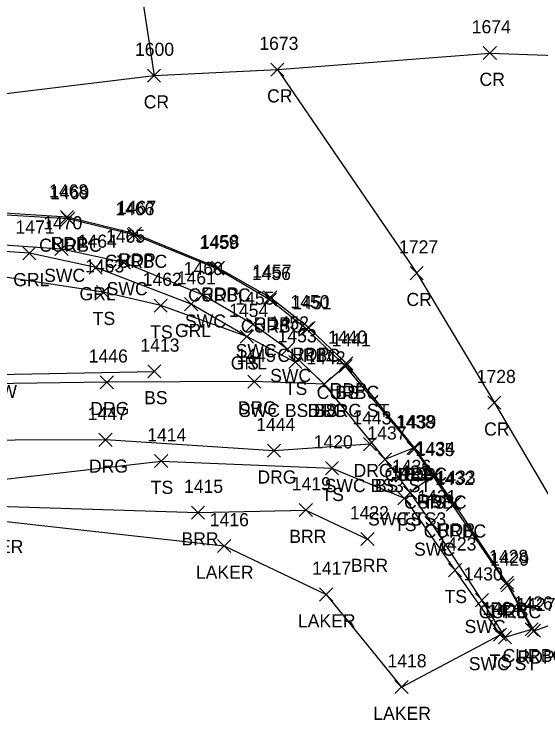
# Model space of a CAD drawing. Extents: x 1716490 to 1717645, y 888034 to 890004.
# Drawn here: x 1717515.4 to 1717595.6, y 888176.8 to 888284.2 of the extents above; entities that cross this region are included whole.
import ezdxf

# ---------------------------------------------------------------- set-up
doc = ezdxf.new("R2010")
doc.units = 0
for name, color, linetype in [('L_A', 7, 'Continuous'), ('L_I', 7, 'Continuous'), ('L_TIC', 7, 'Continuous'), ('LABL', 7, 'Continuous'), ('LAWE', 7, 'Continuous'), ('LELB', 7, 'Continuous'), ('LSOGP', 7, 'Continuous'), ('P_A', 7, 'Continuous'), ('P_I', 7, 'Continuous'), ('P_TIC', 7, 'Continuous'), ('PET', 7, 'Continuous'), ('PRC', 7, 'Continuous'), ('R_A', 7, 'Continuous'), ('R_I', 7, 'Continuous'), ('R_TIC', 7, 'Continuous'), ('RC', 7, 'Continuous'), ('RDG', 7, 'Continuous'), ('RGR', 7, 'Continuous'), ('RSW', 7, 'Continuous'), ('U_A', 7, 'Continuous')]:
    doc.layers.add(name, color=color, linetype=linetype)

msp = doc.modelspace()

# ---------------------------------------------------------------- linework, layer by layer
at = {"layer": 'L_TIC'}
for points in [[(1717527.96, 888240.86), (1717529.96, 888242.86)], [(1717529.96, 888240.86), (1717527.96, 888242.86)], [(1717536.71, 888238.81), (1717538.71, 888240.81)], [(1717538.71, 888238.81), (1717536.71, 888240.81)], [(1717549.82, 888234.09), (1717551.82, 888236.09)], [(1717551.82, 888234.09), (1717549.82, 888236.09)], [(1717557.19, 888230.22), (1717559.19, 888232.22)], [(1717559.19, 888230.22), (1717557.19, 888232.22)], [(1717535.75, 888228.8), (1717537.75, 888230.8)], [(1717537.75, 888228.8), (1717535.75, 888230.8)], [(1717564.85, 888229.61), (1717566.85, 888231.61)], [(1717566.85, 888229.61), (1717564.85, 888231.61)], [(1717561.58, 888226.86), (1717563.58, 888228.86)], [(1717563.58, 888226.86), (1717561.58, 888228.86)], [(1717575.18, 888217.15), (1717577.18, 888219.15)], [(1717577.18, 888217.15), (1717575.18, 888219.15)], [(1717536.79, 888215.15), (1717538.79, 888217.15)], [(1717538.79, 888215.15), (1717536.79, 888217.15)], [(1717570.85, 888215.43), (1717572.85, 888217.43)], [(1717572.85, 888215.43), (1717570.85, 888217.43)], [(1717562.77, 888214.07), (1717564.77, 888216.07)], [(1717564.77, 888214.07), (1717562.77, 888216.07)], [(1717578.16, 888212.91), (1717580.16, 888214.91)], [(1717580.16, 888212.91), (1717578.16, 888214.91)], [(1717573.8, 888209.49), (1717575.8, 888211.49)], [(1717575.8, 888209.49), (1717573.8, 888211.49)], [(1717574.66, 888210.35), (1717576.66, 888212.35)], [(1717576.66, 888210.35), (1717574.66, 888212.35)], [(1717542.38, 888207.31), (1717544.38, 888209.31)], [(1717544.38, 888207.31), (1717542.38, 888209.31)], [(1717558.79, 888207.7), (1717560.79, 888209.7)], [(1717560.79, 888207.7), (1717558.79, 888209.7)], [(1717568.18, 888203.29), (1717570.18, 888205.29)], [(1717570.18, 888203.29), (1717568.18, 888205.29)], [(1717546.36, 888202.24), (1717548.36, 888204.24)], [(1717548.36, 888202.24), (1717546.36, 888204.24)], [(1717581.49, 888198.54), (1717583.49, 888200.54)], [(1717583.49, 888198.54), (1717581.49, 888200.54)], [(1717561.88, 888194.85), (1717563.88, 888196.85)], [(1717563.88, 888194.85), (1717561.88, 888196.85)], [(1717588.34, 888188.72), (1717590.34, 888190.72)], [(1717590.34, 888188.72), (1717588.34, 888190.72)], [(1717573.35, 888180.76), (1717575.35, 888182.76)], [(1717575.35, 888180.76), (1717573.35, 888182.76)]]:
    msp.add_lwpolyline(points, dxfattribs=at)
at = {"layer": 'LABL'}
msp.add_lwpolyline([(1717444.3, 888210.77), (1717472.09, 888208.53), (1717508.03, 888209.44), (1717543.38, 888208.31), (1717559.79, 888208.7), (1717569.18, 888204.29)], dxfattribs=at)
at = {"layer": 'LAWE'}
msp.add_lwpolyline([(1717435.89, 888208.95), (1717475.75, 888203.81), (1717512.34, 888207.14), (1717547.36, 888203.24), (1717562.88, 888195.85), (1717574.35, 888181.76)], dxfattribs=at)
at = {"layer": 'LELB'}
for points in [[(1717558.19, 888231.22), (1717550.82, 888235.09), (1717537.71, 888239.81), (1717528.96, 888241.86), (1717509.31, 888244.84), (1717490.29, 888244.53), (1717470.3, 888242.67), (1717436.84, 888242.33)], [(1717436.26, 888226.8), (1717464.72, 888228.24), (1717507.39, 888229.25), (1717536.75, 888229.8)], [(1717565.85, 888230.61), (1717562.58, 888227.86)], [(1717571.85, 888216.43), (1717576.18, 888218.15)], [(1717436.47, 888211.21), (1717466.2, 888211.2), (1717507.83, 888212.69), (1717537.79, 888216.15), (1717563.77, 888215.07), (1717574.8, 888210.49), (1717582.49, 888199.54), (1717589.34, 888189.72)], [(1717579.16, 888213.91), (1717575.66, 888211.35)]]:
    msp.add_lwpolyline(points, dxfattribs=at)
at = {"layer": 'LSOGP'}
msp.add_lwpolyline([(1717512.34, 888207.14), (1717547.36, 888203.24), (1717562.88, 888195.85), (1717574.35, 888181.76), (1717589.34, 888189.72), (1717590.1, 888189.33), (1717594.16, 888190.55), (1717594.52, 888190.33), (1717606.37, 888194.61), (1717616.38, 888200.56), (1717616.48, 888200.84), (1717619.62, 888200.38), (1717628.46, 888203.99), (1717634.03, 888211.44), (1717635.99, 888213.88), (1717640, 888226.53), (1717642.15, 888234.3), (1717638.96, 888241.6), (1717636.39, 888248.28), (1717633.57, 888258.39), (1717629.03, 888277.17), (1717629.47, 888295.32)], dxfattribs=at)
at = {"layer": 'P_TIC'}
for points in [[(1717586.78, 888277.25), (1717588.78, 888279.25)], [(1717588.78, 888277.25), (1717586.78, 888279.25)], [(1717535.7, 888273.82), (1717537.7, 888275.82)], [(1717537.7, 888273.82), (1717535.7, 888275.82)], [(1717535.7, 888273.82), (1717537.7, 888275.82)], [(1717537.7, 888273.82), (1717535.7, 888275.82)], [(1717554.46, 888274.73), (1717556.46, 888276.73)], [(1717556.46, 888274.73), (1717554.46, 888276.73)], [(1717554.46, 888274.73), (1717556.46, 888276.73)], [(1717556.46, 888274.73), (1717554.46, 888276.73)], [(1717522.47, 888252.27), (1717524.47, 888254.27)], [(1717524.47, 888252.27), (1717522.47, 888254.27)], [(1717532.81, 888249.76), (1717534.81, 888251.76)], [(1717534.81, 888249.76), (1717532.81, 888251.76)], [(1717545.42, 888244.58), (1717547.42, 888246.58)], [(1717547.42, 888244.58), (1717545.42, 888246.58)], [(1717575.67, 888243.75), (1717577.67, 888245.75)], [(1717577.67, 888243.75), (1717575.67, 888245.75)], [(1717553.37, 888240.05), (1717555.37, 888242.05)], [(1717555.37, 888240.05), (1717553.37, 888242.05)], [(1717559.23, 888235.41), (1717561.23, 888237.41)], [(1717561.23, 888235.41), (1717559.23, 888237.41)], [(1717564.95, 888230.02), (1717566.95, 888232.02)], [(1717566.95, 888230.02), (1717564.95, 888232.02)], [(1717587.48, 888224.03), (1717589.48, 888226.03)], [(1717589.48, 888224.03), (1717587.48, 888226.03)], [(1717575.4, 888217.12), (1717577.4, 888219.12)], [(1717577.4, 888217.12), (1717575.4, 888219.12)], [(1717578.26, 888213.07), (1717580.26, 888215.07)], [(1717580.26, 888213.07), (1717578.26, 888215.07)], [(1717581.37, 888208.7), (1717583.37, 888210.7)], [(1717583.37, 888208.7), (1717581.37, 888210.7)], [(1717589.37, 888196.64), (1717591.37, 888198.64)], [(1717591.37, 888196.64), (1717589.37, 888198.64)], [(1717593.52, 888189.33), (1717595.52, 888191.33)], [(1717595.52, 888189.33), (1717593.52, 888191.33)]]:
    msp.add_lwpolyline(points, dxfattribs=at)
at = {"layer": 'PET'}
msp.add_lwpolyline([(1717594.52, 888190.33), (1717590.37, 888197.64), (1717582.37, 888209.7), (1717579.26, 888214.07), (1717576.4, 888218.12), (1717565.95, 888231.02), (1717560.23, 888236.41), (1717554.37, 888241.05), (1717546.42, 888245.58), (1717533.81, 888250.76), (1717523.47, 888253.27), (1717509.16, 888254.18), (1717488.82, 888253.07), (1717469.07, 888251.8), (1717449.41, 888250.83), (1717439.89, 888250.33)], dxfattribs=at)
at = {"layer": 'PRC'}
for points in [[(1717529.47, 888316.75), (1717534.37, 888290.09), (1717536.7, 888274.82)], [(1717436.1, 888262.99), (1717458.49, 888266.27), (1717492.01, 888269.4), (1717536.7, 888274.82), (1717555.46, 888275.73), (1717587.78, 888278.25), (1717619.44, 888277.12), (1717629.03, 888277.17)], [(1717555.46, 888275.73), (1717576.67, 888244.75), (1717588.48, 888225.03), (1717606.37, 888194.61)]]:
    msp.add_lwpolyline(points, dxfattribs=at)
at = {"layer": 'R_TIC'}
for points in [[(1717522.63, 888252.01), (1717524.63, 888254.01)], [(1717524.63, 888252.01), (1717522.63, 888254.01)], [(1717532.61, 888249.56), (1717534.61, 888251.56)], [(1717534.61, 888249.56), (1717532.61, 888251.56)], [(1717521.62, 888247.42), (1717523.62, 888249.42)], [(1717523.62, 888247.42), (1717521.62, 888249.42)], [(1717516.74, 888246.77), (1717518.74, 888248.77)], [(1717518.74, 888246.77), (1717516.74, 888248.77)], [(1717531.13, 888245.38), (1717533.13, 888247.38)], [(1717533.13, 888245.38), (1717531.13, 888247.38)], [(1717526.82, 888244.62), (1717528.82, 888246.62)], [(1717528.82, 888244.62), (1717526.82, 888246.62)], [(1717545.3, 888244.43), (1717547.3, 888246.43)], [(1717547.3, 888244.43), (1717545.3, 888246.43)], [(1717543.05, 888240.46), (1717545.05, 888242.46)], [(1717545.05, 888240.46), (1717543.05, 888242.46)], [(1717553.33, 888239.71), (1717555.33, 888241.71)], [(1717555.33, 888239.71), (1717553.33, 888241.71)], [(1717541.34, 888239.03), (1717543.34, 888241.03)], [(1717543.34, 888239.03), (1717541.34, 888241.03)], [(1717550.76, 888235.95), (1717552.76, 888237.95)], [(1717552.76, 888235.95), (1717550.76, 888237.95)], [(1717558.89, 888235.25), (1717560.89, 888237.25)], [(1717560.89, 888235.25), (1717558.89, 888237.25)], [(1717549.82, 888234.09), (1717551.82, 888236.09)], [(1717551.82, 888234.09), (1717549.82, 888236.09)], [(1717556.01, 888232.18), (1717558.01, 888234.18)], [(1717558.01, 888232.18), (1717556.01, 888234.18)], [(1717564.85, 888229.61), (1717566.85, 888231.61)], [(1717566.85, 888229.61), (1717564.85, 888231.61)], [(1717528.51, 888227.14), (1717530.51, 888229.14)], [(1717530.51, 888227.14), (1717528.51, 888229.14)], [(1717550.96, 888227.25), (1717552.96, 888229.25)], [(1717552.96, 888227.25), (1717550.96, 888229.25)], [(1717561.58, 888226.86), (1717563.58, 888228.86)], [(1717563.58, 888226.86), (1717561.58, 888228.86)], [(1717561.58, 888226.86), (1717563.58, 888228.86)], [(1717563.58, 888226.86), (1717561.58, 888228.86)], [(1717528.31, 888218.39), (1717530.31, 888220.39)], [(1717530.31, 888218.39), (1717528.31, 888220.39)], [(1717568.56, 888217.73), (1717570.56, 888219.73)], [(1717570.56, 888217.73), (1717568.56, 888219.73)], [(1717575.18, 888217.15), (1717577.18, 888219.15)], [(1717577.18, 888217.15), (1717575.18, 888219.15)], [(1717553.95, 888216.73), (1717555.95, 888218.73)], [(1717555.95, 888216.73), (1717553.95, 888218.73)], [(1717570.85, 888215.43), (1717572.85, 888217.43)], [(1717572.85, 888215.43), (1717570.85, 888217.43)], [(1717578.16, 888212.91), (1717580.16, 888214.91)], [(1717580.16, 888212.91), (1717578.16, 888214.91)], [(1717574.66, 888210.35), (1717576.66, 888212.35)], [(1717576.66, 888210.35), (1717574.66, 888212.35)], [(1717581.13, 888208.51), (1717583.13, 888210.51)], [(1717583.13, 888208.51), (1717581.13, 888210.51)], [(1717577.9, 888205.74), (1717579.9, 888207.74)], [(1717579.9, 888205.74), (1717577.9, 888207.74)], [(1717589.51, 888196.23), (1717591.51, 888198.23)], [(1717591.51, 888196.23), (1717589.51, 888198.23)], [(1717585.59, 888193.98), (1717587.59, 888195.98)], [(1717587.59, 888193.98), (1717585.59, 888195.98)], [(1717593.16, 888189.55), (1717595.16, 888191.55)], [(1717595.16, 888189.55), (1717593.16, 888191.55)], [(1717589.1, 888188.33), (1717591.1, 888190.33)], [(1717591.1, 888188.33), (1717589.1, 888190.33)]]:
    msp.add_lwpolyline(points, dxfattribs=at)
at = {"layer": 'RC'}
msp.add_lwpolyline([(1717594.16, 888190.55), (1717590.51, 888197.23), (1717582.13, 888209.51), (1717579.16, 888213.91), (1717576.18, 888218.15), (1717565.85, 888230.61), (1717559.89, 888236.25), (1717554.33, 888240.71), (1717546.3, 888245.43), (1717533.61, 888250.56), (1717523.63, 888253.01), (1717509.03, 888253.88), (1717488.9, 888252.85), (1717469.14, 888251.62), (1717449.34, 888250.48), (1717439.5, 888250.04)], dxfattribs=at)
at = {"layer": 'RDG'}
for points in [[(1717562.58, 888227.86), (1717551.96, 888228.25), (1717529.51, 888228.14), (1717486.8, 888227.54)], [(1717569.56, 888218.73), (1717554.95, 888217.73), (1717529.31, 888219.39), (1717488.02, 888219.24)]]:
    msp.add_lwpolyline(points, dxfattribs=at)
at = {"layer": 'RGR'}
msp.add_lwpolyline([(1717550.82, 888235.09), (1717542.34, 888240.03), (1717527.82, 888245.62), (1717517.74, 888247.77), (1717508.58, 888248.41), (1717489.51, 888247.72), (1717469.57, 888246.67), (1717449.39, 888245.32), (1717432.29, 888244.31)], dxfattribs=at)
at = {"layer": 'RSW'}
msp.add_lwpolyline([(1717590.1, 888189.33), (1717586.59, 888194.98), (1717578.9, 888206.74), (1717575.66, 888211.35), (1717571.85, 888216.43), (1717562.58, 888227.86), (1717557.01, 888233.18), (1717551.76, 888236.95), (1717544.05, 888241.46), (1717532.13, 888246.38), (1717522.62, 888248.42), (1717508.75, 888249.36), (1717489.32, 888248.52), (1717469.4, 888247.38), (1717449.77, 888246.07), (1717439.35, 888245.71)], dxfattribs=at)

# ---------------------------------------------------------------- texts
at = {"layer": 'L_A'}
for s, p in [('TS', (1717527.37, 888236.86)), ('TS', (1717536.12, 888234.81)), ('TS', (1717549.23, 888230.09)), ('TS', (1717556.6, 888226.22)), ('BS', (1717564.29, 888225.61)), ('BS', (1717535.19, 888224.8)), ('BS', (1717561.03, 888222.86)), ('BS', (1717574.63, 888213.15)), ('BS', (1717570.29, 888211.43)), ('TS', (1717536.2, 888211.15)), ('TS', (1717562.18, 888210.07)), ('TS', (1717577.57, 888208.91)), ('TS', (1717574.07, 888206.35)), ('TS', (1717573.21, 888205.49)), ('BRR', (1717540.87, 888203.31)), ('BRR', (1717557.28, 888203.7)), ('LAKER', (1717508.05, 888202.14)), ('BRR', (1717566.67, 888199.29)), ('LAKER', (1717543.07, 888198.24)), ('TS', (1717580.9, 888194.54)), ('LAKER', (1717558.59, 888190.85)), ('TS', (1717587.75, 888184.72)), ('LAKER', (1717570.06, 888176.76))]:
    msp.add_text(s, height=2, dxfattribs=at).set_placement(p)
at = {"layer": 'L_I'}
for s, p in [('1463', (1717526.22, 888244.86)), ('1462', (1717534.97, 888242.81)), ('1454', (1717548.13, 888238.09)), ('1453', (1717555.5, 888234.22)), ('1441', (1717563.73, 888233.61)), ('1413', (1717534.62, 888232.8)), ('1442', (1717559.89, 888230.86)), ('1438', (1717573.49, 888221.15)), ('1414', (1717535.66, 888219.15)), ('1437', (1717569.16, 888219.43)), ('1420', (1717560.99, 888218.07)), ('1435', (1717576.46, 888216.91)), ('1436', (1717572.91, 888214.35)), ('1421', (1717572.68, 888213.49)), ('1419', (1717557.66, 888211.7)), ('1415', (1717541.26, 888211.31)), ('1422', (1717566.49, 888207.29)), ('1416', (1717545.18, 888206.24)), ('1423', (1717579.8, 888202.54)), ('1417', (1717560.75, 888198.85)), ('1424', (1717586.65, 888192.72)), ('1418', (1717572.22, 888184.76))]:
    msp.add_text(s, height=2, dxfattribs=at).set_placement(p)
at = {"layer": 'P_A'}
for s, p in [('CR', (1717586.22, 888273.25)), ('CR', (1717553.9, 888270.73)), ('CR', (1717553.9, 888270.73)), ('CR', (1717535.13, 888269.82)), ('CR', (1717535.13, 888269.82)), ('RDP', (1717520.95, 888248.27)), ('RDP', (1717531.29, 888245.76)), ('RDP', (1717543.91, 888240.58)), ('CR', (1717575.1, 888239.75)), ('RDP', (1717551.86, 888236.05)), ('RDP', (1717557.72, 888231.41)), ('RDP', (1717563.43, 888226.02)), ('CR', (1717586.92, 888220.03)), ('RDP', (1717573.89, 888213.12)), ('RDP', (1717576.74, 888209.07)), ('RDP', (1717579.86, 888204.7)), ('RDP', (1717587.85, 888192.64)), ('RDP', (1717592.01, 888185.33))]:
    msp.add_text(s, height=2, dxfattribs=at).set_placement(p)
at = {"layer": 'P_I'}
for s, p in [('1674', (1717585.04, 888281.25)), ('1673', (1717552.72, 888278.73)), ('1673', (1717552.72, 888278.73)), ('1600', (1717533.8, 888277.82)), ('1600', (1717533.8, 888277.82)), ('1468', (1717520.73, 888256.27)), ('1467', (1717531.07, 888253.76)), ('1458', (1717543.73, 888248.58)), ('1727', (1717573.98, 888247.75)), ('1457', (1717551.67, 888244.05)), ('1450', (1717557.45, 888239.41)), ('1440', (1717563.17, 888234.02)), ('1728', (1717585.79, 888228.03)), ('1439', (1717573.7, 888221.12)), ('1434', (1717576.56, 888217.07)), ('1433', (1717579.68, 888212.7)), ('1428', (1717587.67, 888200.64)), ('1427', (1717591.82, 888193.33))]:
    msp.add_text(s, height=2, dxfattribs=at).set_placement(p)
at = {"layer": 'R_A'}
for s, p in [('CURBC', (1717519.22, 888248.01)), ('CURBC', (1717529.19, 888245.56)), ('GRL', (1717515.28, 888242.77)), ('SWC', (1717519.98, 888243.42)), ('GRL', (1717525.36, 888240.62)), ('SWC', (1717529.49, 888241.38)), ('CURBC', (1717541.89, 888240.43)), ('SWC', (1717541.41, 888236.46)), ('GRL', (1717539.88, 888235.03)), ('CURBC', (1717549.91, 888235.71)), ('SWC', (1717549.12, 888231.95)), ('CURBC', (1717555.47, 888231.25)), ('GRL', (1717548.37, 888230.09)), ('SWC', (1717554.37, 888228.18)), ('CURBC', (1717561.44, 888225.61)), ('DRG', (1717549.44, 888223.25)), ('DRG', (1717527, 888223.14)), ('SWC BS5 DRG ST', (1717549.62, 888222.86)), ('DRG', (1717560.07, 888222.86)), ('DRG', (1717526.8, 888214.39)), ('DRG', (1717567.05, 888213.73)), ('DRG', (1717552.43, 888212.73)), ('CURBC', (1717571.77, 888213.15)), ('SWC BS3 ST', (1717562.66, 888211.43)), ('CURBC', (1717574.74, 888208.91)), ('SWC TS3', (1717569.26, 888206.35)), ('CURBC', (1717577.72, 888204.51)), ('SWC', (1717576.26, 888201.74)), ('CURBC', (1717586.09, 888192.23)), ('SWC', (1717583.95, 888189.98)), ('CURBC', (1717589.74, 888185.55)), ('SWC ST', (1717584.59, 888184.33))]:
    msp.add_text(s, height=2, dxfattribs=at).set_placement(p)
at = {"layer": 'R_I'}
for s, p in [('1469', (1717520.89, 888256.01)), ('1466', (1717530.81, 888253.56)), ('1470', (1717519.84, 888251.42)), ('1471', (1717515.62, 888250.77)), ('1465', (1717529.39, 888249.38)), ('1464', (1717525.08, 888248.62)), ('1459', (1717543.6, 888248.43)), ('1460', (1717541.22, 888244.46)), ('1456', (1717551.58, 888243.71)), ('1461', (1717540.16, 888243.03)), ('1455', (1717549.07, 888239.95)), ('1451', (1717557.76, 888239.25)), ('1454', (1717548.13, 888238.09)), ('1452', (1717554.32, 888236.18)), ('1441', (1717563.73, 888233.61)), ('1446', (1717526.76, 888231.14)), ('1445', (1717549.26, 888231.25)), ('1442', (1717559.89, 888230.86)), ('1442', (1717559.89, 888230.86)), ('1447', (1717526.62, 888222.39)), ('1443', (1717566.87, 888221.73)), ('1438', (1717573.49, 888221.15)), ('1444', (1717552.25, 888220.73)), ('1437', (1717569.16, 888219.43)), ('1435', (1717576.46, 888216.91)), ('1436', (1717572.91, 888214.35)), ('1432', (1717579.44, 888212.51)), ('1431', (1717576.77, 888209.74)), ('1429', (1717587.81, 888200.23)), ('1430', (1717583.81, 888197.98)), ('1426', (1717591.41, 888193.55)), ('1425', (1717587.4, 888192.33))]:
    msp.add_text(s, height=2, dxfattribs=at).set_placement(p)
at = {"layer": 'U_A'}
msp.add_text('GUYW', height=2, dxfattribs=at).set_placement((1717507.53, 888225.75))

doc.saveas('drawing.dxf')
